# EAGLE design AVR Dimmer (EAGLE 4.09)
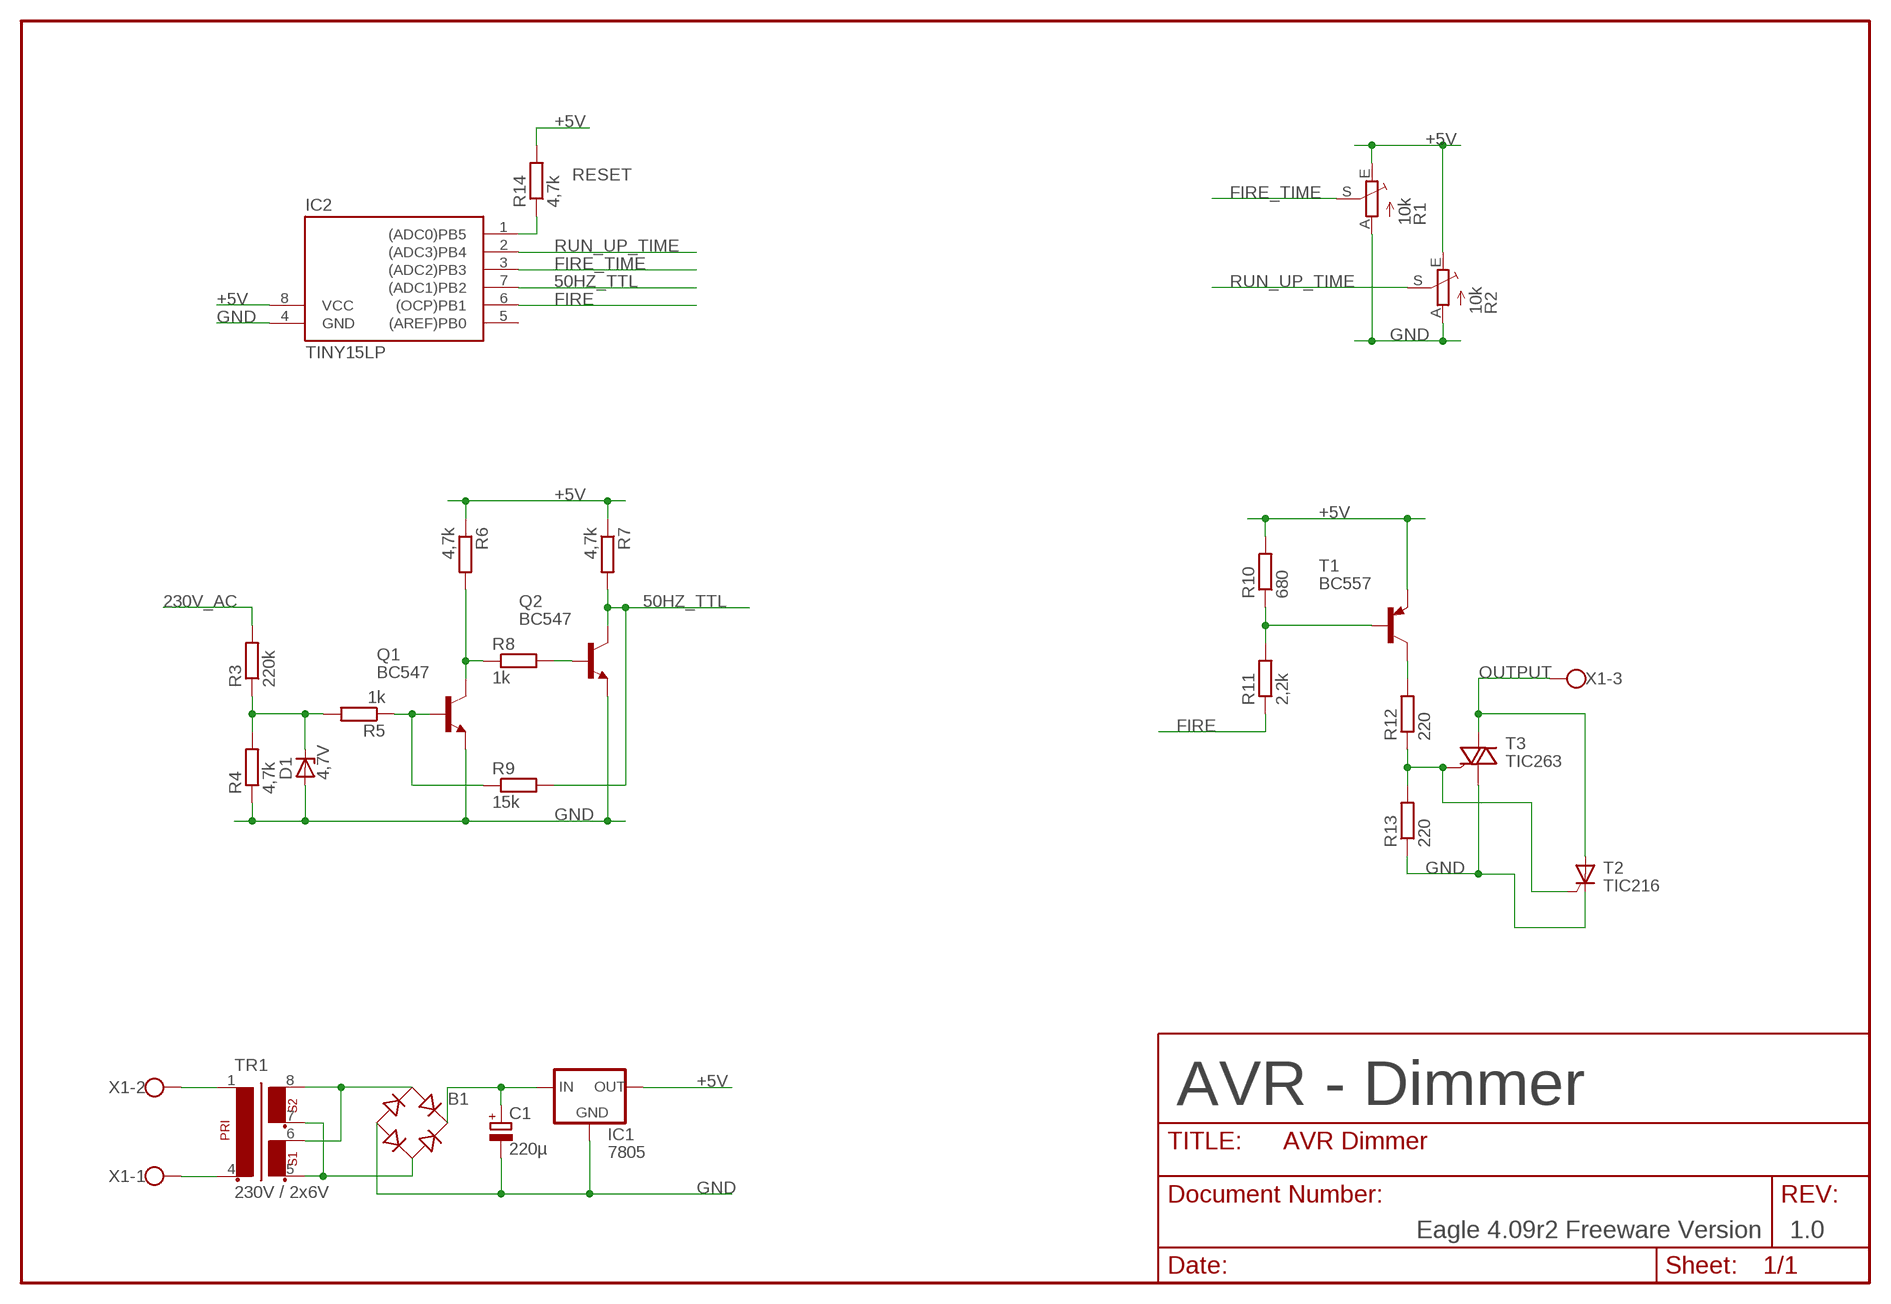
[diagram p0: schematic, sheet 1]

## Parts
B1  RB1A  [RB1A]
C1  220µ  CPOL-EUE22-6AXIAL  [E22-6]
D1  4,7V  ZENER-DIODEDO34-7  [DO34Z7]
IC1  7805  78XXS  [78XXS]
IC2  TINY15LP  [DIL08]
Q1  BC547  [TO92]
Q2  BC547  [TO92]
R1  10k  TRIM_EU-S64Y  [S64Y]
R2  10k  TRIM_EU-S64Y  [S64Y]
R3  220k  R-EU_0207/10  [0207/10]
R4  4,7k  R-EU_0207/2V  [0207/2V]
R5  1k  R-EU_0207/2V  [0207/2V]
R6  4,7k  R-EU_0207/2V  [0207/2V]
R7  4,7k  R-EU_0207/2V  [0207/2V]
R8  1k  R-EU_0207/2V  [0207/2V]
R9  15k  R-EU_0207/2V  [0207/2V]
R10  680  R-EU_0207/2V  [0207/2V]
R11  2,2k  R-EU_0207/2V  [0207/2V]
R12  220  R-EU_0207/2V  [0207/2V]
R13  220  R-EU_0207/2V  [0207/2V]
R14  4,7k  R-EU_0207/2V  [0207/2V]
T1  BC557  [TO92]
T2  TIC216  TIC126  [TO220CS]
T3  TIC263  TIC253  [TO218DS]
TR1  230V / 2x6V  EE20-2  [EE20-2]
X1  W237-103  [W237-103]

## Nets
6V_AC: B1.AC1 TR1.6 TR1.8
50HZ_TTL: IC2.7((ADC1)PB2) Q2.3(C) R7.2 R9.2
230V_AC: R3.2 TR1.4 X1.1
+5V: IC1.OUT IC2.8(VCC) R1.E R2.E R6.1 R7.1 R10.2 R14.2 T1.1(E)
FIRE: IC2.6((OCP)PB1) R11.1
FIRE_TIME: IC2.3((ADC2)PB3) R1.S
GND: B1.- C1.- D1.A IC1.GND IC2.4(GND) Q1.1(E) Q2.1(E) R1.A R2.A R4.1 R13.1 T2.C T3.A1 TR1.1 X1.2
N$1: IC2.1((ADC0)PB5) R14.1
N$2: R12.1 R13.2 T2.G T3.G
N$4: B1.AC2 TR1.5 TR1.7
N$5: Q1.2(B) R5.1 R9.1
N$6: D1.C R3.1 R4.2 R5.2
N$7: B1.+ C1.+ IC1.IN
N$9: R12.2 T1.3(C)
N$10: Q1.3(C) R6.2 R8.1
N$12: Q2.2(B) R8.2
N$15: R10.1 R11.2 T1.2(B)
OUTPUT: T2.A T3.A2 X1.3
RUN_UP_TIME: IC2.2((ADC3)PB4) R2.S
Unconnected: IC2.5((AREF)PB0)

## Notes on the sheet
- RESET
- AVR - Dimmer
- Eagle 4.09r2 Freeware Version | 1.0

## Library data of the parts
B1 = rectifier:RB1A: RECTIFIER 1 A
C1 = rcl:CPOL-EU: POLARIZED CAPACITOR, European symbol
D1 = diode:ZENER-DIODE: Z-Diode
IC1 = v-reg:78XXS: VOLTAGE REGULATOR
IC2 = avr:TINY15L: MICROCONTROLLER 2.7 V 1 Kbytes FLASH 64 bytes EEPROM 4-channel 10 bit ADC
Q1 Q2 = transistor-npn:BC547*: NPN Transistor
R1 R2 = pot:TRIM_EU-: POTENTIOMETER
R3-R14 = rcl:R-EU_: RESISTOR, European symbol
T1 = transistor-pnp:BC557: PNP Transistor
T2 = triac:TIC126: THYRISTOR
T3 = triac:TIC253: TRIAC
TR1 = trafo:EE20-2: TRANSFORMER 1 primary winding, 2 secondary windings ERA
X1 = con-wago-500:W237-103: WAGO SCREW CLAMP

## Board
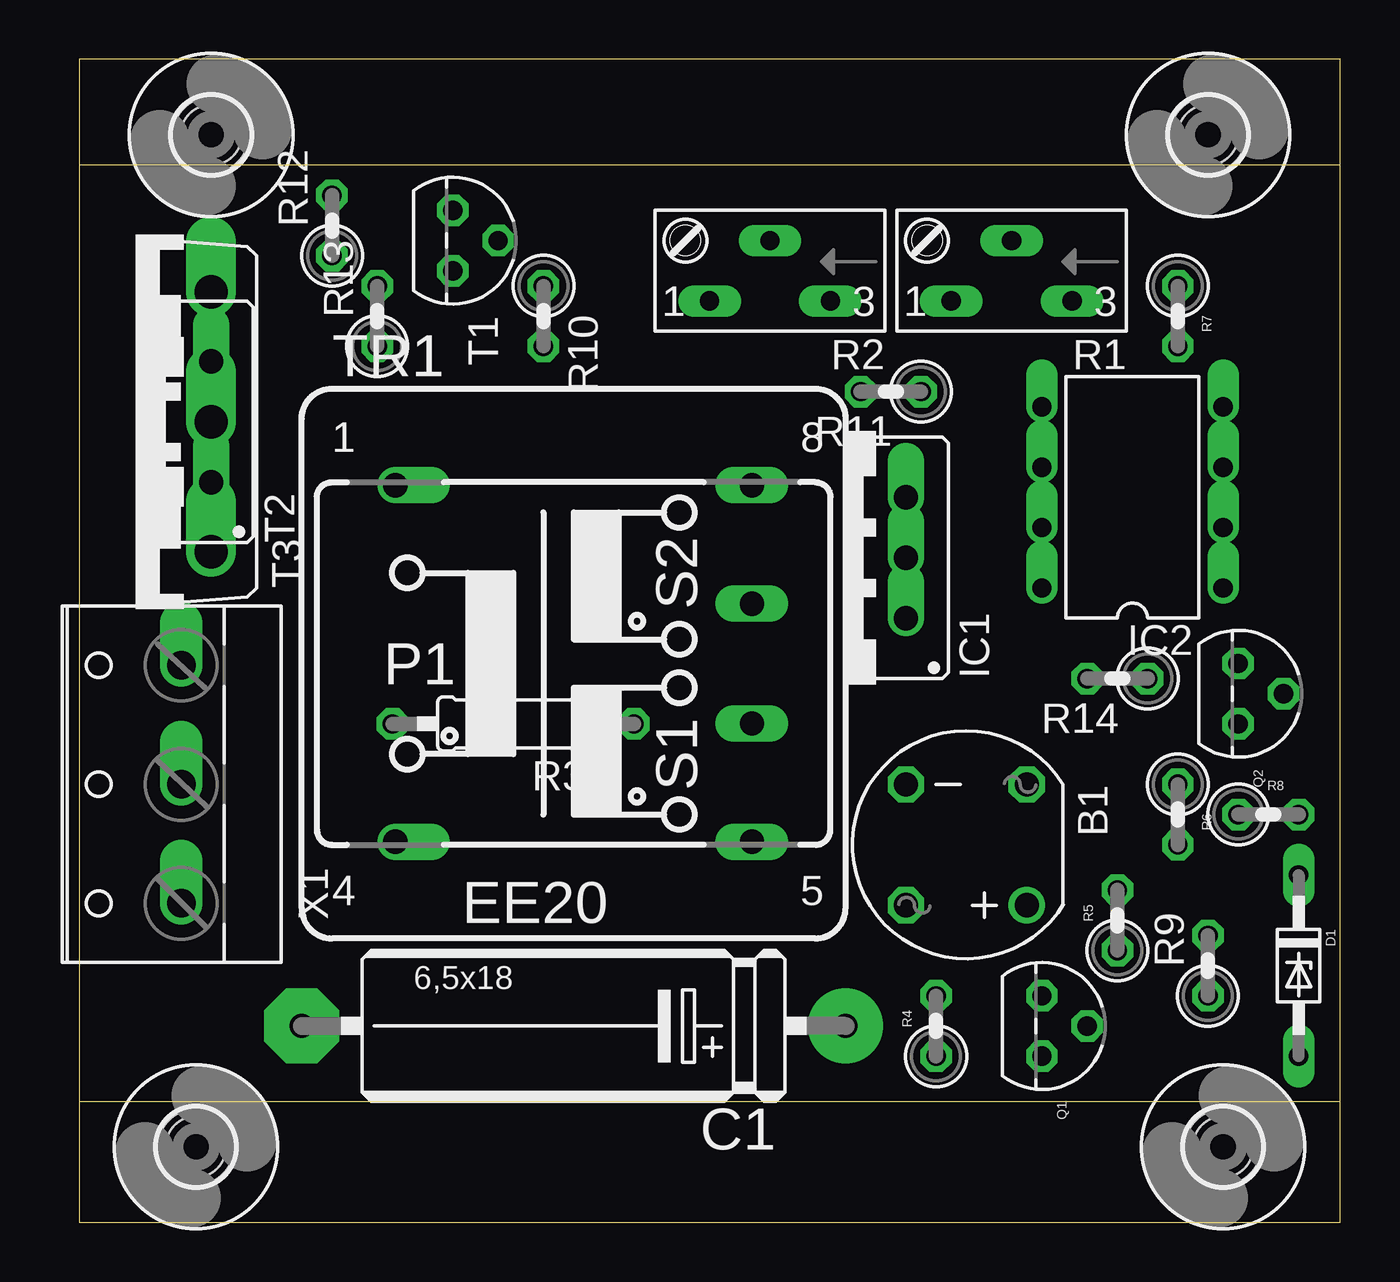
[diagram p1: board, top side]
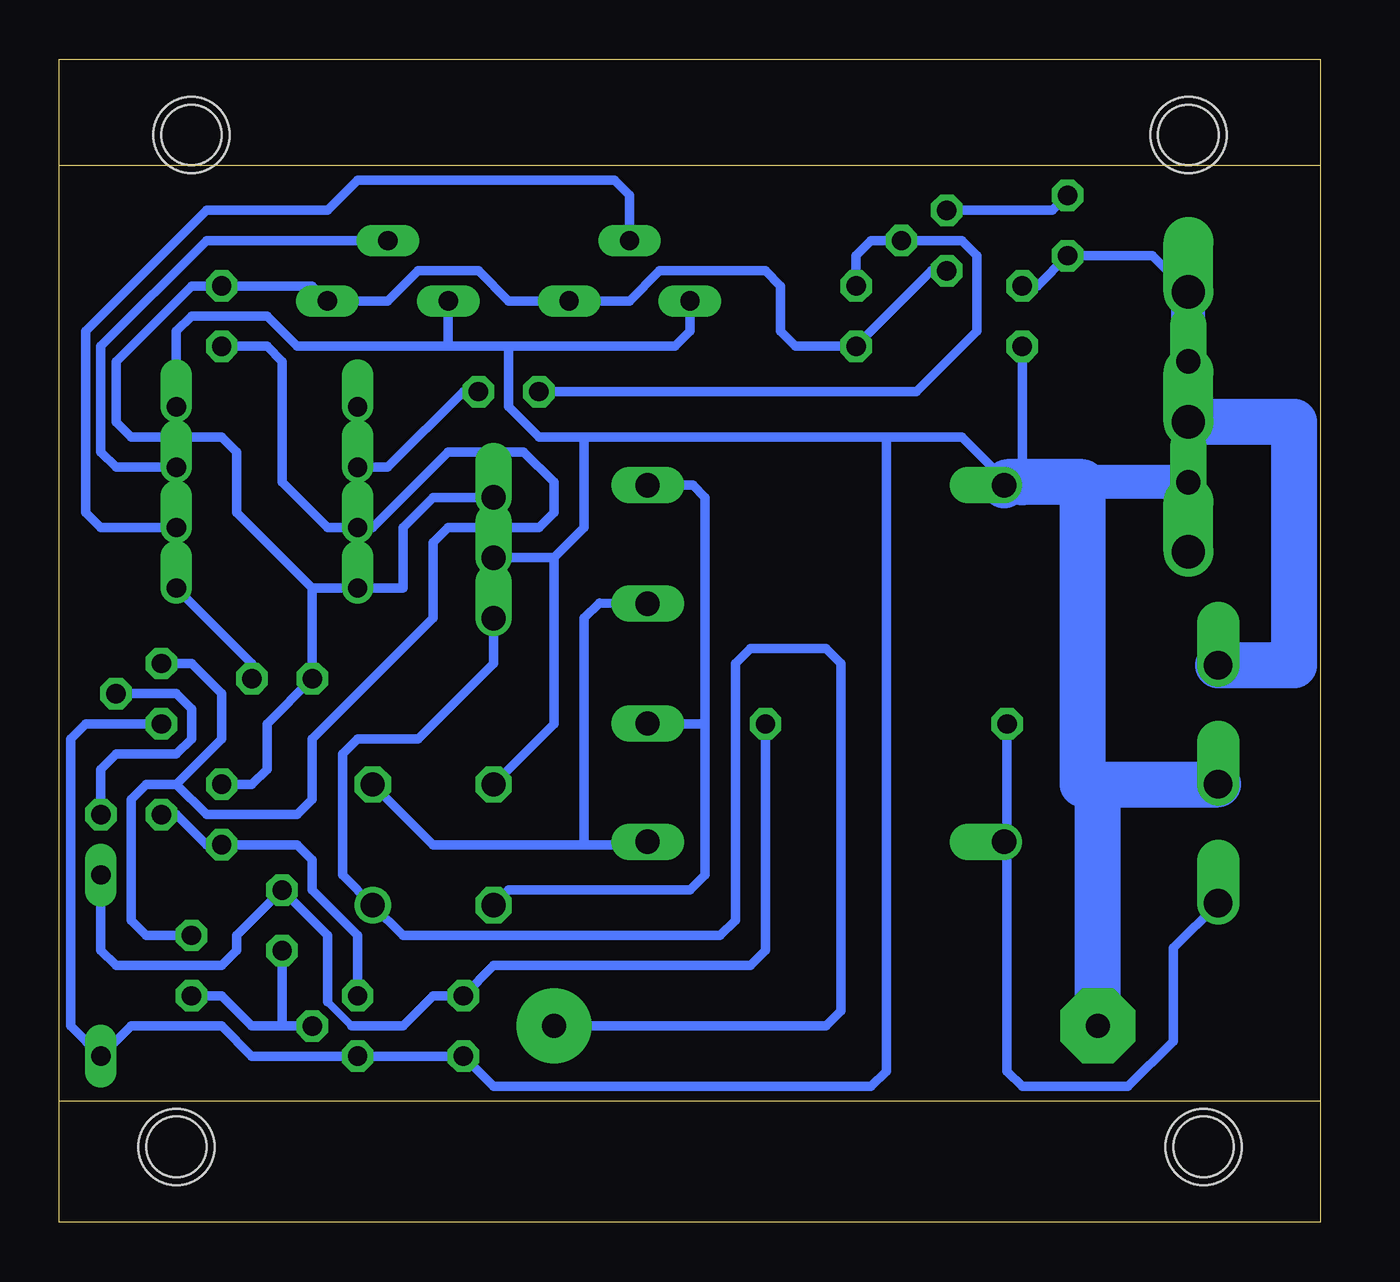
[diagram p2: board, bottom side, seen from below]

Size 53.01 x 48.88 mm. Coordinates in mm from the lower left corner, seen from the top.
Outline: 53.01,44.44 53.01,0 0,0 0,5.08
Outline: 53.01,44.44 53.01,48.88 0,48.88 0,44.44
Outline: 0,44.44 0,5.08
Outline: 53.01,44.44 0,44.44
Outline: 0,5.08 53.01,5.08
Copper layers used: Bottom
Holes 2.54 mm at 4.92,3.17 47.46,45.72 48.09,3.17 5.55,45.72

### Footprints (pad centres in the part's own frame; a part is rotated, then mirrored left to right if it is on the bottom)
RB1A = drill 1.016 round: + -2.54,2.54 | drill 1.016 octagon: - 2.54,-2.54; AC1 2.54,2.54; AC2 -2.54,-2.54
E22-6 = drill 1.016 pad 3.15 round: + -11.43,0 | drill 1.016 pad 3.15 octagon: - 11.43,0
DO34Z7 = drill 0.813 long: A 3.81,0; C -3.81,0
78XXS = drill 1.016 offset: GND 0,-2.54; IN -2.54,-2.54; OUT 2.54,-2.54
DIL08 = drill 0.813 offset: 1 -3.81,-3.81; 2 -1.27,-3.81; 3 1.27,-3.81; 4 3.81,-3.81; 5 3.81,3.81; 6 1.27,3.81; 7 -1.27,3.81; 8 -3.81,3.81
TO92 = drill 0.813 octagon: 1 1.27,0; 2 0,1.905; 3 -1.27,0
S64Y = drill 0.813 long: A 2.54,1.27; E -2.54,1.27; S 0,-1.27
0207/10 = drill 0.813 octagon: 1 -5.08,0; 2 5.08,0
0207/2V = drill 0.813 octagon: 1 -1.27,0; 2 1.27,0
TO220CS = drill 1.016 offset: A 0,-2.54; C -2.54,-2.54; G 2.54,-2.54
TO218DS = drill 1.397 offset: A1 -5.461,-3.175; A2 0,-3.175; G 5.461,-3.175
EE20-2 = drill 1.016 offset: 1 -7.493,7.493; 4 -7.493,-7.493 | drill 1.016 long: 5 7.493,-7.493; 6 7.493,-2.515; 7 7.493,2.515; 8 7.493,7.493
3,2 = hole 3.2: 0,0
W237-103 = drill 1.194 offset: 1 -5,-1.29; 2 0,-1.29; 3 5,-1.29

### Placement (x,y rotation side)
B1  37.3,15.87 180 top
C1  20.79,8.25 180 top
D1  51.27,10.79 270 top
IC1  32.22,27.94 90 top
IC2  44.28,30.48 90 top
Q1  40.48,8.25 270 top
Q2  48.73,22.22 270 top
R1  39.2,40 180 top
R2  29.04,40 180 top
R3  18.25,20.95 180 top
R4  36.03,8.25 90 top
R5  43.65,12.7 90 top
R6  46.19,17.14 270 top
R7  46.19,38.09 270 top
R8  50,17.14 0 top
R9  47.46,10.79 90 top
R10  19.52,38.09 270 top
R11  34.12,34.92 180 top
R12  10.63,41.91 90 top
R13  12.54,38.09 90 top
R14  43.65,22.86 180 top
T1  15.71,41.27 270 top
T2  3.01,33.65 90 top
T3  2.38,33.65 90 top
TR1  20.79,23.49 0 top
U$1  [3,2]  4.92,3.17 0 top
U$2  [3,2]  47.46,45.72 0 top
U$3  [3,2]  5.55,45.72 0 top
U$4  [3,2]  48.09,3.17 0 top
X1  3.01,18.41 90 top

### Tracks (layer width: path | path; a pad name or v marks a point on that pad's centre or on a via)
6V_AC
  Bottom 0.406: 25.87,20.95 25.87,30.48 26.38,30.98 TR1.8 | TR1.6 28.41,20.98 28.41,20.95 25.87,20.95 | B1.AC1 34.12,13.96 26.5,13.96 25.87,14.6 25.87,20.95
50HZ_TTL
  Bottom 0.406: R9.2 49.37,12.06 50,12.7 50,17.77 49.37,18.41 48.09,18.41 | 48.09,18.41 46.19,20.32 46.19,22.22 47.46,23.49 Q2.3 | R7.2 44.28,36.82 43.65,36.19 43.65,31.11 41.74,29.21 IC2.7 39.84,29.21 36.66,32.38 33.49,32.38 32.22,31.11 32.22,29.84 32.85,29.21 36.66,29.21 37.3,28.57 37.3,25.39 42.38,20.32 42.38,17.77 43.02,17.14 46.82,17.14 48.09,18.41
230V_AC
  Bottom 0.406: X1.1 6.18,11.53 6.18,7.62 8.09,5.71 12.54,5.71 13.17,6.34 13.17,15.87 TR1.4 13.17,16.12 R3.2
+5V
  Bottom 0.406: T1.1 16.34,40 R10.2 22.06,36.82 22.7,37.46 22.7,39.37 23.33,40 27.77,40 29.04,38.73 R2.E 34.12,38.73 35.39,40 37.94,40 39.2,38.73 R1.E 42.38,39.37 R7.1 47.46,39.37 50.63,36.19 50.63,33.65 50,33.02 46.19,33.02 45.55,32.38 45.55,29.84 42.38,26.66 | IC1.OUT 37.3,30.48 38.57,29.21 38.57,26.66 IC2.8 42.38,26.66 | R6.1 44.92,18.41 44.28,19.05 44.28,20.95 R14.2 42.38,26.66
FIRE
  Bottom 0.406: IC2.6 39.2,31.75 36.03,34.92 R11.1
FIRE_TIME
  Bottom 0.406: IC2.3 50.63,31.75 51.27,32.38 51.27,36.82 46.82,41.27 R1.S
GND
  Bottom 0.406: Q2.1 51.91,20.95 52.54,20.32 52.54,8.25 D1.A 50,8.25 46.19,8.25 44.92,6.98 Q1.1 R4.1 34.76,5.71 18.88,5.71 18.25,6.34 18.25,33.02 | B1.- 32.22,20.95 32.22,27.94 | 34.12,36.82 34.12,34.28 32.85,33.02 30.95,33.02 | 30.95,33.02 30.95,29.21 32.22,27.94 | 34.12,36.82 36.66,36.82 | 36.66,36.82 R1.A | 32.22,27.94 IC1.GND | 34.12,36.82 27.14,36.82 26.5,37.46 R2.A | 13.17,31.11 15.08,33.02 18.25,33.02 | 12.54,31.11 R13.1 | 36.66,36.82 43.02,36.82 44.28,38.09 47.46,38.09 48.09,37.46 IC2.4 | 18.25,33.02 30.95,33.02
  Bottom 1.422: 10,31.11 T2.C T3.A1
  Bottom 1.93: 9.36,18.41 X1.2 | 9.36,18.41 10,18.41 10,31.11 12.54,31.11 13.17,31.11 TR1.1 | C1.- 9.36,18.41
N$1
  Bottom 0.406: IC2.1 44.92,23.49 R14.1
N$2
  Bottom 0.406: R13.2 11.9,39.37 R12.1 7.07,40.63 T3.G
  Bottom 1.422: T2.G T3.G
N$4
  Bottom 0.406: TR1.7 30.31,26.03 30.95,25.39 30.95,25.37 30.95,15.87 | B1.AC2 37.3,15.87 30.95,15.87 | TR1.5 28.41,15.87 30.95,15.87
N$5
  Bottom 0.406: 43.65,8.25 44.92,8.25 46.19,9.52 R9.1 | 43.65,8.25 R5.1 | Q1.2 43.65,8.25
N$6
  Bottom 0.305: 40.73,8.25 41.74,9.27
  Bottom 0.406: R3.1 23.33,11.43 23.96,10.79 34.76,10.79 R4.2 37.3,9.52 38.57,8.25 40.73,8.25 | D1.C 51.27,11.43 50.63,10.79 46.19,10.79 45.55,11.43 45.55,12.06 R5.2 41.74,12.06 41.74,9.27
N$7
  Bottom 0.406: IC1.IN 34.76,23.49 37.94,20.32 40.48,20.32 41.11,19.68 41.11,14.6 B1.+ 38.57,12.06 25.23,12.06 24.6,12.7 24.6,23.49 23.96,24.12 20.79,24.12 20.15,23.49 20.15,8.88 20.79,8.25 C1.+
N$9
  Bottom 0.406: R12.2 11.27,42.54 T1.3
N$10
  Bottom 0.406: Q1.3 40.48,12.06 42.38,13.96 42.38,15.23 43.02,15.87 R6.2 46.82,15.87 48.09,17.14 R8.1
N$12
  Bottom 0.406: Q2.2 48.09,22.22 47.46,21.59 47.46,20.32 48.09,19.68 50.63,19.68 51.27,19.05 R8.2
N$15
  Bottom 0.406: R10.1 19.52,40.63 18.88,41.27 T1.2 15.08,41.27 14.44,40.63 14.44,37.46 16.98,34.92 R11.2
OUTPUT
  Bottom 1.93: X1.3 1.1,23.41 1.1,33.65 T2.A
RUN_UP_TIME
  Bottom 0.406: IC2.2 51.27,29.21 51.91,29.84 51.91,37.46 46.82,42.54 41.74,42.54 40.48,43.81 29.68,43.81 29.04,43.18 R2.S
